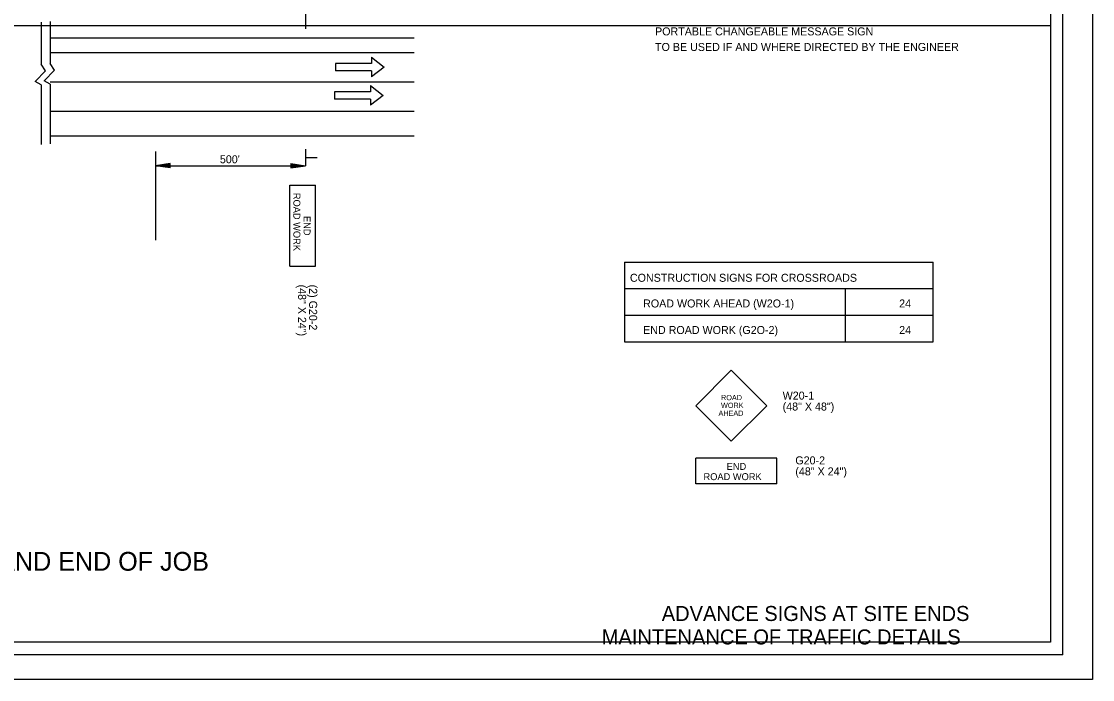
# Model space of a CAD drawing. Extents: x 1373222 to 1374279, y 380783 to 380996.
# Drawn here: x 1373384 to 1373555.3, y 380783.1 to 380888.5 of the extents above; entities that cross this region are included whole.
import ezdxf

# ---------------------------------------------------------------- set-up
doc = ezdxf.new("R2010")
doc.units = 0
for name, color, linetype in [('R_Border', 7, 'Continuous'), ('R_Border Title', 7, 'Continuous'), ('R_Draft', 7, 'Continuous'), ('R_No Plot', 7, 'Continuous')]:
    doc.layers.add(name, color=color, linetype=linetype)

msp = doc.modelspace()

# ---------------------------------------------------------------- linework, layer by layer
at = {"layer": 'R_Border'}
for q in [(1373550.56, 380992.59), (1373234.38, 380787.13)]:
    msp.add_line((1373550.56, 380787.13), q, dxfattribs=at)
at = {"layer": 'R_Draft'}
for p, q in [((1373429.44, 380889.95), (1373429.44, 380887.31)), ((1373387.11, 380888.4), (1373387.11, 380881.64)), ((1373388.56, 380888.5), (1373388.56, 380881.75)), ((1373446.78, 380885.81), (1373388.56, 380885.81)), ((1373446.78, 380883.46), (1373388.56, 380883.46)), ((1373439.95, 380882.76), (1373439.95, 380881.78)), ((1373439.95, 380882.76), (1373441.98, 380881.19)), ((1373439.95, 380881.78), (1373434.19, 380881.78)), ((1373434.19, 380881.78), (1373434.19, 380880.61)), ((1373439.95, 380880.61), (1373434.19, 380880.61)), ((1373441.98, 380881.19), (1373439.95, 380879.63)), ((1373439.95, 380880.61), (1373439.95, 380879.63)), ((1373387.11, 380878.35), (1373387.11, 380868.82)), ((1373446.78, 380878.77), (1373388.56, 380878.77)), ((1373388.56, 380878.45), (1373388.56, 380868.93)), ((1373439.8, 380877.25), (1373434.04, 380877.25)), ((1373434.04, 380877.25), (1373434.04, 380876.08)), ((1373439.8, 380878.23), (1373439.8, 380877.25)), ((1373439.8, 380878.23), (1373441.83, 380876.66)), ((1373439.8, 380876.08), (1373434.04, 380876.08)), ((1373441.83, 380876.66), (1373439.8, 380875.1)), ((1373439.8, 380876.08), (1373439.8, 380875.1)), ((1373446.78, 380874.07), (1373388.56, 380874.07)), ((1373446.78, 380870.16), (1373388.56, 380870.16)), ((1373405.44, 380867.67), (1373405.44, 380853.49)), ((1373429.44, 380868.05), (1373429.44, 380865.41)), ((1373407.79, 380865.76), (1373405.44, 380865.41)), ((1373405.44, 380865.41), (1373429.44, 380865.41)), ((1373407.79, 380865.05), (1373405.44, 380865.41)), ((1373407.79, 380865.7), (1373405.84, 380865.41)), ((1373407.79, 380865.11), (1373405.84, 380865.41)), ((1373407.79, 380865.64), (1373406.24, 380865.41)), ((1373407.79, 380865.17), (1373406.24, 380865.41)), ((1373407.79, 380865.58), (1373406.63, 380865.41)), ((1373407.79, 380865.23), (1373406.63, 380865.41)), ((1373407.79, 380865.52), (1373407.03, 380865.41)), ((1373407.79, 380865.29), (1373407.03, 380865.41)), ((1373407.79, 380865.46), (1373407.42, 380865.41)), ((1373407.79, 380865.35), (1373407.42, 380865.41)), ((1373407.79, 380865.05), (1373407.79, 380865.76)), ((1373427.09, 380865.76), (1373429.44, 380865.41)), ((1373427.09, 380865.76), (1373427.09, 380865.05)), ((1373427.09, 380865.7), (1373429.05, 380865.41)), ((1373427.09, 380865.64), (1373428.64, 380865.41)), ((1373427.09, 380865.58), (1373428.25, 380865.41)), ((1373427.09, 380865.52), (1373427.85, 380865.41)), ((1373427.09, 380865.46), (1373427.46, 380865.41)), ((1373427.09, 380865.05), (1373429.44, 380865.41)), ((1373427.09, 380865.29), (1373427.85, 380865.41)), ((1373427.09, 380865.17), (1373428.64, 380865.41)), ((1373427.09, 380865.11), (1373429.05, 380865.41)), ((1373427.09, 380865.23), (1373428.25, 380865.41)), ((1373427.09, 380865.35), (1373427.46, 380865.41)), ((1373429.47, 380866.73), (1373431.28, 380866.73)), ((1373426.91, 380849.32), (1373426.91, 380862.31)), ((1373426.91, 380862.31), (1373430.99, 380862.31)), ((1373430.99, 380849.32), (1373430.99, 380862.31)), ((1373480.44, 380849.96), (1373529.83, 380849.96)), ((1373529.83, 380837.21), (1373529.83, 380849.96)), ((1373426.91, 380849.32), (1373430.99, 380849.32)), ((1373529.83, 380845.71), (1373480.44, 380845.71)), ((1373515.73, 380845.71), (1373515.73, 380837.21)), ((1373497.53, 380832.68), (1373491.84, 380826.98)), ((1373503.23, 380826.98), (1373497.53, 380832.68)), ((1373497.53, 380821.29), (1373491.84, 380826.98)), ((1373503.23, 380826.98), (1373497.53, 380821.29)), ((1373504.83, 380818.59), (1373491.84, 380818.59)), ((1373491.84, 380814.51), (1373491.84, 380818.59)), ((1373504.83, 380814.51), (1373504.83, 380818.59)), ((1373504.83, 380814.51), (1373491.84, 380814.51))]:
    msp.add_line(p, q, dxfattribs=at)
for points in [[(1373387.11, 380878.35), (1373386.19, 380878.9), (1373387.84, 380880.61), (1373387.11, 380881.64)], [(1373388.56, 380878.45), (1373387.63, 380879.01), (1373389.28, 380880.71), (1373388.56, 380881.75)], [(1373480.44, 380849.96), (1373480.44, 380841.46), (1373529.83, 380841.46)], [(1373480.44, 380841.46), (1373480.44, 380837.21), (1373529.83, 380837.21)]]:
    msp.add_lwpolyline(points, dxfattribs=at)
at = {"layer": 'R_No Plot'}
for points in [[(1373221.98, 380996.49), (1373555.32, 380996.49), (1373555.32, 380783.15), (1373221.98, 380783.15)], [(1373236.38, 380990.59), (1373485.92, 380990.59), (1373485.92, 380980.71), (1373503.46, 380980.71), (1373527.56, 380980.71), (1373527.56, 380958.38), (1373548.56, 380958.38), (1373548.56, 380789.13), (1373236.38, 380789.13)], [(1373236.38, 380887.86), (1373548.56, 380887.86), (1373548.56, 380789.13), (1373236.38, 380789.13)]]:
    msp.add_lwpolyline(points, close=True, dxfattribs=at)

# ---------------------------------------------------------------- texts
at = {"layer": 'R_Border Title'}
for s, p in [('ADVANCE SIGNS AT SITE ENDS', (1373486.4, 380792.53)), ('MAINTENANCE OF TRAFFIC DETAILS', (1373476.8, 380788.78))]:
    msp.add_text(s, height=2.4, dxfattribs=at).set_placement(p)
at = {"layer": 'R_Draft'}
for s, height, p in [('PORTABLE CHANGEABLE MESSAGE SIGN', 1.28, (1373485.33, 380886.27)), ('TO BE USED IF AND WHERE DIRECTED BY THE ENGINEER', 1.28, (1373485.33, 380883.78)), ("500'", 1.28, (1373415.72, 380865.8)), ('CONSTRUCTION SIGNS FOR CROSSROADS', 1.28, (1373481.31, 380846.83)), ('ROAD WORK AHEAD (W2O-1)', 1.28, (1373483.42, 380842.72)), ('24', 1.28, (1373524.38, 380842.72)), ('END ROAD WORK (G2O-2)', 1.28, (1373483.42, 380838.47)), ('24', 1.28, (1373524.38, 380838.47)), ('G20-2', 1.28, (1373507.77, 380817.6)), ('END', 1.109, (1373496.79, 380816.72)), ('(48" X 24")', 1.28, (1373507.77, 380815.84)), ('ROAD WORK', 1.109, (1373493.08, 380815.08)), ('ADVANCE SIGNS AT BEGINNING AND END OF JOB', 3.0041, (1373316.2, 380800.58))]:
    msp.add_text(s, height=height, dxfattribs=at).set_placement(p)
for s, height, rotation, p in [('ROAD WORK', 1.109, 270, (1373427.48, 380861.07)), ('END', 1.109, 270, (1373429.12, 380857.36)), ('(48" X 24")', 1.28, 270, (1373428.24, 380846.38)), ('(2) G20-2', 1.28, 270, (1373430, 380846.38)), ('W20-1', 1.28, 360, (1373505.74, 380827.97)), ('WORK', 0.839, 0, (1373495.88, 380826.63)), ('ROAD', 0.839, 0.0004, (1373495.89, 380827.88)), ('(48" X 48")', 1.28, 360, (1373505.74, 380826.22)), ('AHEAD', 0.839, 0.0006, (1373495.48, 380825.37))]:
    msp.add_text(s, height=height, rotation=rotation, dxfattribs=at).set_placement(p)

doc.saveas('drawing.dxf')
